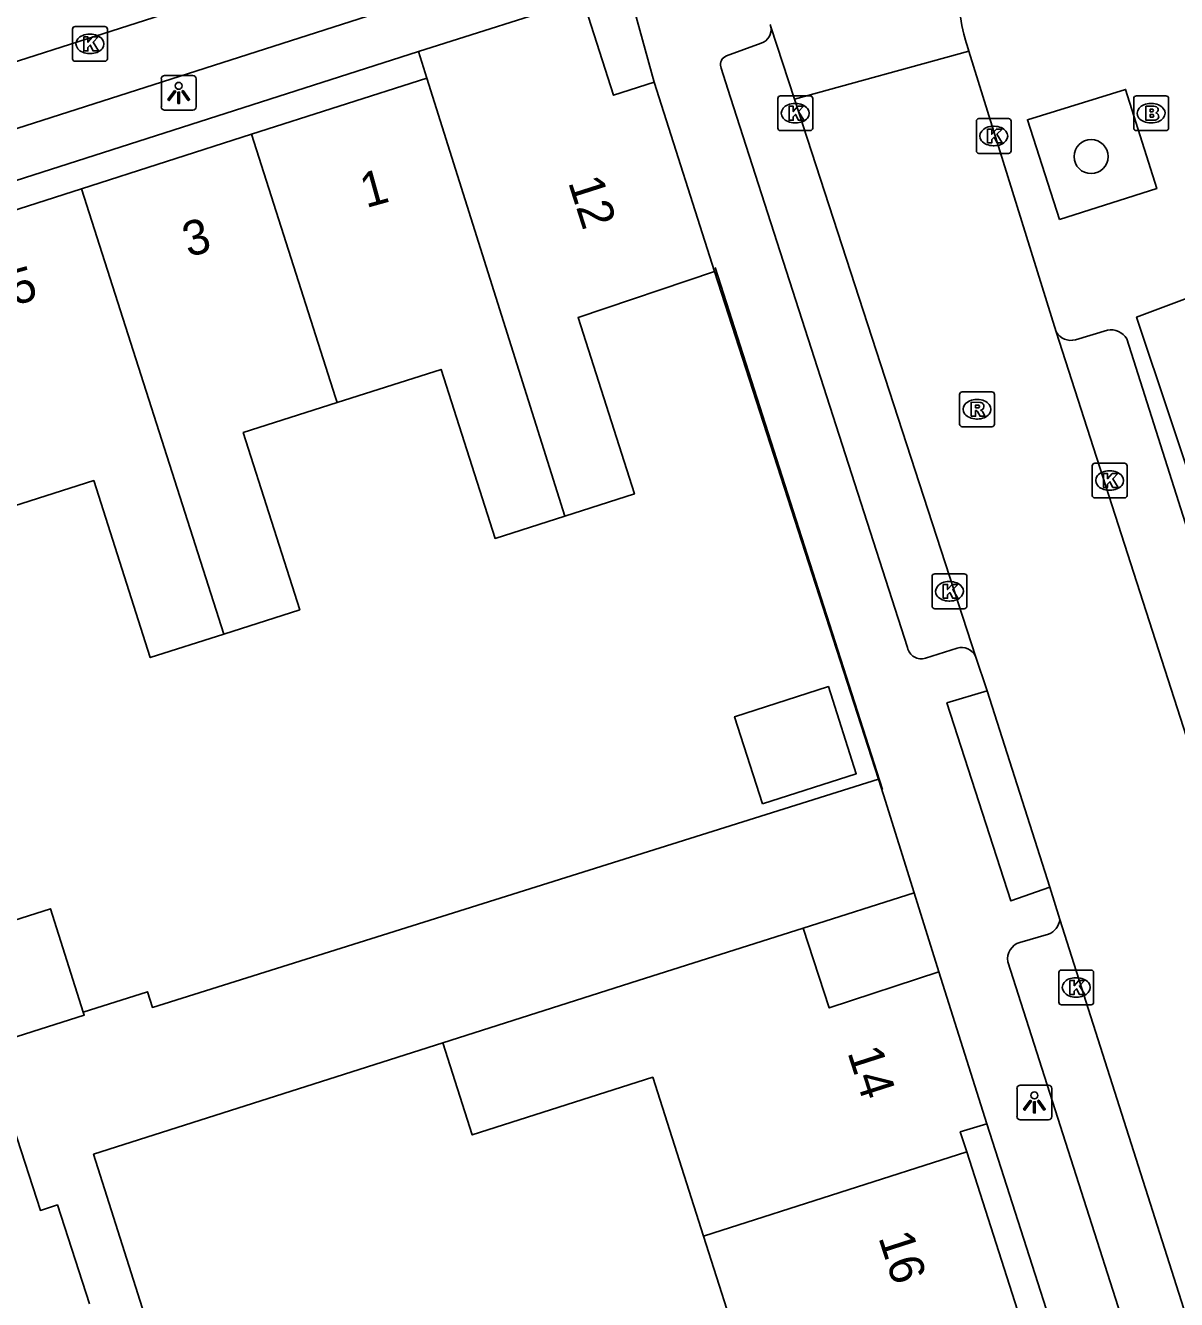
# Model space of a CAD drawing. Extents: x 159718 to 160783, y 383290 to 384030.
# Drawn here: x 160111.85 to 160144.93, y 383640.55 to 383677.17 of the extents above; entities that cross this region are included whole.
import ezdxf

# ---------------------------------------------------------------- set-up
doc = ezdxf.new("R2010")
doc.units = 0
for name, color, linetype in [('IMGEO_Boom', 7, 'Continuous'), ('IMGEO_Brandkraan', 7, 'Continuous'), ('IMGEO_Kolk', 7, 'Continuous'), ('IMGEO_Lichtpunt', 7, 'Continuous'), ('IMGEO_Muur', 7, 'Continuous'), ('IMGEO_Pand', 7, 'Continuous'), ('IMGEO_Pand_nummerreeks', 7, 'Continuous'), ('IMGEO_Rijbaan_lokaal_open', 7, 'Continuous'), ('IMGEO_Rioolput', 7, 'Continuous'), ('IMGEO_Voetpad_open', 7, 'Continuous')]:
    doc.layers.add(name, color=color, linetype=linetype)

msp = doc.modelspace()

# ---------------------------------------------------------------- linework, layer by layer
at = {"layer": 'IMGEO_Boom'}
msp.add_circle((160142.474, 383673.403), 0.489, dxfattribs=at)
at = {"layer": 'IMGEO_Brandkraan'}
for p, q in [((160143.699, 383674.224), (160143.699, 383675.076)), ((160143.774, 383675.15), (160144.626, 383675.15)), ((160144.187, 383674.93), (160144.212, 383674.93)), ((160144.7, 383675.076), (160144.7, 383674.224)), ((160144.626, 383674.15), (160143.774, 383674.15)), ((160144.21, 383674.37), (160144.185, 383674.37))]:
    msp.add_line(p, q, dxfattribs=at)
for points in [[(160143.699, 383674.224), (160143.699, 383675.076)], [(160143.774, 383675.15), (160144.626, 383675.15)], [(160144.047, 383674.85), (160144.047, 383674.45), (160144.26, 383674.45)], [(160144.278, 383674.85), (160144.047, 383674.85)], [(160144.7, 383675.076), (160144.7, 383674.224)], [(160144.226, 383674.769), (160144.172, 383674.769), (160144.172, 383674.693)], [(160144.172, 383674.693), (160144.225, 383674.693)], [(160144.234, 383674.617), (160144.172, 383674.617), (160144.172, 383674.536)], [(160144.172, 383674.536), (160144.234, 383674.536)], [(160144.626, 383674.15), (160143.774, 383674.15)]]:
    msp.add_lwpolyline(points, dxfattribs=at)
for centre, radius, start, end in [((160143.776, 383675.074), 0.0765, 91.552, 178.448), ((160143.776, 383675.074), 0.0765, 91.552, 178.448), ((160144.282, 383674.705), 0.145, 59.4692, 91.5367), ((160144.307, 383674.752), 0.0922, 285.5137, 58.1501), ((160144.624, 383675.074), 0.0765, 1.552, 88.448), ((160144.624, 383675.074), 0.0765, 1.552, 88.448), ((160144.227, 383674.731), 0.0379, 267.8285, 90.9355), ((160144.235, 383674.576), 0.0404, 269.8759, 90.5077), ((160144.266, 383674.701), 0.251, 268.6676, 293.5347), ((160144.312, 383674.56), 0.105, 301.3115, 78.989), ((160143.776, 383674.226), 0.0765, 181.552, 268.448), ((160143.776, 383674.226), 0.0765, 181.552, 268.448), ((160144.624, 383674.226), 0.0765, 271.552, 358.448), ((160144.624, 383674.226), 0.0765, 271.552, 358.448)]:
    msp.add_arc(centre, radius, start, end, dxfattribs=at)
for centre, major_axis, ratio, start_param, end_param in [((160144.186, 383674.65), (-0.387, 0.002), 0.722429, 4.712389, 7.853982), ((160144.211, 383674.65), (-0.39, 0.002), 0.717154, 1.570796, 4.712389)]:
    msp.add_ellipse(centre, major_axis=major_axis, ratio=ratio, start_param=start_param, end_param=end_param, dxfattribs=at)
at = {"layer": 'IMGEO_Kolk'}
for p, q in [((160113.203, 383676.217), (160113.203, 383677.069)), ((160113.278, 383677.143), (160114.13, 383677.143)), ((160114.204, 383677.069), (160114.204, 383676.217)), ((160113.691, 383676.923), (160113.716, 383676.923)), ((160113.714, 383676.363), (160113.689, 383676.363)), ((160114.13, 383676.143), (160113.278, 383676.143)), ((160133.472, 383674.223), (160133.472, 383675.075)), ((160133.547, 383675.149), (160134.399, 383675.149)), ((160133.96, 383674.929), (160133.985, 383674.929)), ((160134.473, 383675.075), (160134.473, 383674.223)), ((160139.252, 383674.495), (160140.104, 383674.495)), ((160134.399, 383674.149), (160133.547, 383674.149)), ((160133.983, 383674.369), (160133.958, 383674.369)), ((160139.177, 383673.569), (160139.177, 383674.421)), ((160139.665, 383674.275), (160139.69, 383674.275)), ((160140.178, 383674.421), (160140.178, 383673.569)), ((160139.688, 383673.715), (160139.663, 383673.715)), ((160140.104, 383673.495), (160139.252, 383673.495)), ((160142.581, 383664.592), (160143.433, 383664.592)), ((160142.506, 383663.666), (160142.506, 383664.518)), ((160142.994, 383664.372), (160143.019, 383664.372)), ((160143.507, 383664.518), (160143.507, 383663.666)), ((160143.017, 383663.812), (160142.992, 383663.812)), ((160143.433, 383663.592), (160142.581, 383663.592)), ((160137.904, 383660.482), (160137.904, 383661.334)), ((160137.979, 383661.408), (160138.831, 383661.408)), ((160138.905, 383661.334), (160138.905, 383660.482)), ((160138.392, 383661.188), (160138.417, 383661.188)), ((160138.415, 383660.628), (160138.39, 383660.628)), ((160138.831, 383660.408), (160137.979, 383660.408)), ((160141.545, 383649.096), (160141.545, 383649.948)), ((160141.62, 383650.022), (160142.472, 383650.022)), ((160142.546, 383649.948), (160142.546, 383649.096)), ((160142.033, 383649.802), (160142.058, 383649.802)), ((160142.056, 383649.242), (160142.031, 383649.242)), ((160142.472, 383649.022), (160141.62, 383649.022))]:
    msp.add_line(p, q, dxfattribs=at)
for points in [[(160113.203, 383676.217), (160113.203, 383677.069)], [(160113.278, 383677.143), (160114.13, 383677.143)], [(160114.204, 383677.069), (160114.204, 383676.217)], [(160113.524, 383676.843), (160113.647, 383676.843), (160113.647, 383676.692), (160113.777, 383676.843), (160113.941, 383676.843), (160113.795, 383676.692), (160113.948, 383676.443), (160113.796, 383676.443), (160113.711, 383676.607), (160113.647, 383676.54), (160113.647, 383676.443), (160113.524, 383676.443), (160113.524, 383676.843)], [(160114.13, 383676.143), (160113.278, 383676.143)], [(160133.472, 383674.223), (160133.472, 383675.075)], [(160133.547, 383675.149), (160134.399, 383675.149)], [(160133.793, 383674.849), (160133.916, 383674.849), (160133.916, 383674.698), (160134.046, 383674.849), (160134.21, 383674.849), (160134.064, 383674.698), (160134.217, 383674.449), (160134.065, 383674.449), (160133.98, 383674.613), (160133.916, 383674.546), (160133.916, 383674.449), (160133.793, 383674.449), (160133.793, 383674.849)], [(160134.473, 383675.075), (160134.473, 383674.223)], [(160139.252, 383674.495), (160140.104, 383674.495)], [(160134.399, 383674.149), (160133.547, 383674.149)], [(160139.177, 383673.569), (160139.177, 383674.421)], [(160139.498, 383674.195), (160139.621, 383674.195), (160139.621, 383674.044), (160139.751, 383674.195), (160139.915, 383674.195), (160139.769, 383674.044), (160139.922, 383673.795), (160139.77, 383673.795), (160139.685, 383673.959), (160139.621, 383673.892), (160139.621, 383673.795), (160139.498, 383673.795), (160139.498, 383674.195)], [(160140.178, 383674.421), (160140.178, 383673.569)], [(160140.104, 383673.495), (160139.252, 383673.495)], [(160142.581, 383664.592), (160143.433, 383664.592)], [(160142.506, 383663.666), (160142.506, 383664.518)], [(160142.827, 383664.292), (160142.95, 383664.292), (160142.95, 383664.141), (160143.08, 383664.292), (160143.244, 383664.292), (160143.098, 383664.141), (160143.251, 383663.892), (160143.099, 383663.892), (160143.014, 383664.056), (160142.95, 383663.989), (160142.95, 383663.892), (160142.827, 383663.892), (160142.827, 383664.292)], [(160143.507, 383664.518), (160143.507, 383663.666)], [(160143.433, 383663.592), (160142.581, 383663.592)], [(160137.904, 383660.482), (160137.904, 383661.334)], [(160137.979, 383661.408), (160138.831, 383661.408)], [(160138.905, 383661.334), (160138.905, 383660.482)], [(160138.225, 383661.108), (160138.348, 383661.108), (160138.348, 383660.957), (160138.478, 383661.108), (160138.642, 383661.108), (160138.496, 383660.957), (160138.649, 383660.708), (160138.497, 383660.708), (160138.412, 383660.872), (160138.348, 383660.805), (160138.348, 383660.708), (160138.225, 383660.708), (160138.225, 383661.108)], [(160138.831, 383660.408), (160137.979, 383660.408)], [(160141.545, 383649.096), (160141.545, 383649.948)], [(160141.62, 383650.022), (160142.472, 383650.022)], [(160142.546, 383649.948), (160142.546, 383649.096)], [(160141.866, 383649.722), (160141.989, 383649.722), (160141.989, 383649.571), (160142.119, 383649.722), (160142.283, 383649.722), (160142.137, 383649.571), (160142.29, 383649.322), (160142.138, 383649.322), (160142.053, 383649.486), (160141.989, 383649.419), (160141.989, 383649.322), (160141.866, 383649.322), (160141.866, 383649.722)], [(160142.472, 383649.022), (160141.62, 383649.022)]]:
    msp.add_lwpolyline(points, dxfattribs=at)
for centre, start, end in [((160113.28, 383677.067), 91.552, 178.448), ((160113.28, 383677.067), 91.552, 178.448), ((160114.128, 383677.067), 1.552, 88.448), ((160114.128, 383677.067), 1.552, 88.448), ((160113.28, 383676.219), 181.552, 268.448), ((160113.28, 383676.219), 181.552, 268.448), ((160114.128, 383676.219), 271.552, 358.448), ((160114.128, 383676.219), 271.552, 358.448), ((160133.549, 383675.073), 91.552, 178.448), ((160133.549, 383675.073), 91.552, 178.448), ((160134.397, 383675.073), 1.552, 88.448), ((160134.397, 383675.073), 1.552, 88.448), ((160139.254, 383674.419), 91.552, 178.448), ((160139.254, 383674.419), 91.552, 178.448), ((160140.102, 383674.419), 1.552, 88.448), ((160140.102, 383674.419), 1.552, 88.448), ((160133.549, 383674.225), 181.552, 268.448), ((160133.549, 383674.225), 181.552, 268.448), ((160134.397, 383674.225), 271.552, 358.448), ((160134.397, 383674.225), 271.552, 358.448), ((160139.254, 383673.571), 181.552, 268.448), ((160139.254, 383673.571), 181.552, 268.448), ((160140.102, 383673.571), 271.552, 358.448), ((160140.102, 383673.571), 271.552, 358.448), ((160142.583, 383664.516), 91.552, 178.448), ((160142.583, 383664.516), 91.552, 178.448), ((160143.431, 383664.516), 1.552, 88.448), ((160143.431, 383664.516), 1.552, 88.448), ((160142.583, 383663.668), 181.552, 268.448), ((160142.583, 383663.668), 181.552, 268.448), ((160143.431, 383663.668), 271.552, 358.448), ((160143.431, 383663.668), 271.552, 358.448), ((160137.981, 383661.332), 91.552, 178.448), ((160137.981, 383661.332), 91.552, 178.448), ((160138.829, 383661.332), 1.552, 88.448), ((160138.829, 383661.332), 1.552, 88.448), ((160137.981, 383660.484), 181.552, 268.448), ((160137.981, 383660.484), 181.552, 268.448), ((160138.829, 383660.484), 271.552, 358.448), ((160138.829, 383660.484), 271.552, 358.448), ((160141.622, 383649.946), 91.552, 178.448), ((160141.622, 383649.946), 91.552, 178.448), ((160142.47, 383649.946), 1.552, 88.448), ((160142.47, 383649.946), 1.552, 88.448), ((160141.622, 383649.098), 181.552, 268.448), ((160141.622, 383649.098), 181.552, 268.448), ((160142.47, 383649.098), 271.552, 358.448), ((160142.47, 383649.098), 271.552, 358.448)]:
    msp.add_arc(centre, 0.0765, start, end, dxfattribs=at)
for centre, major_axis, ratio, start_param, end_param in [((160113.69, 383676.643), (-0.387, 0.002), 0.722429, 4.712389, 7.853982), ((160113.715, 383676.643), (-0.39, 0.002), 0.717154, 1.570796, 4.712389), ((160133.959, 383674.649), (-0.387, 0.002), 0.722429, 4.712389, 7.853982), ((160133.984, 383674.649), (-0.39, 0.002), 0.717154, 1.570796, 4.712389), ((160139.664, 383673.995), (-0.387, 0.002), 0.722429, 4.712389, 7.853982), ((160139.689, 383673.995), (-0.39, 0.002), 0.717154, 1.570796, 4.712389), ((160142.993, 383664.092), (-0.387, 0.002), 0.722429, 4.712389, 7.853982), ((160143.018, 383664.092), (-0.39, 0.002), 0.717154, 1.570796, 4.712389), ((160138.391, 383660.908), (-0.387, 0.002), 0.722429, 4.712389, 7.853982), ((160138.416, 383660.908), (-0.39, 0.002), 0.717154, 1.570796, 4.712389), ((160142.032, 383649.522), (-0.387, 0.002), 0.722429, 4.712389, 7.853982), ((160142.057, 383649.522), (-0.39, 0.002), 0.717154, 1.570796, 4.712389)]:
    msp.add_ellipse(centre, major_axis=major_axis, ratio=ratio, start_param=start_param, end_param=end_param, dxfattribs=at)
at = {"layer": 'IMGEO_Lichtpunt'}
for p, q in [((160115.756, 383675.639), (160115.756, 383674.832)), ((160115.756, 383675.639), (160115.756, 383674.832)), ((160116.658, 383675.734), (160115.85, 383675.734)), ((160116.658, 383675.734), (160115.85, 383675.734)), ((160116.752, 383674.832), (160116.752, 383675.639)), ((160116.752, 383674.832), (160116.752, 383675.639)), ((160115.85, 383674.738), (160116.658, 383674.738)), ((160115.85, 383674.738), (160116.658, 383674.738)), ((160140.345, 383646.619), (160140.345, 383645.812)), ((160140.345, 383646.619), (160140.345, 383645.812)), ((160141.247, 383646.714), (160140.439, 383646.714)), ((160141.247, 383646.714), (160140.439, 383646.714)), ((160141.341, 383645.812), (160141.341, 383646.619)), ((160141.341, 383645.812), (160141.341, 383646.619)), ((160140.439, 383645.718), (160141.247, 383645.718)), ((160140.439, 383645.718), (160141.247, 383645.718))]:
    msp.add_line(p, q, dxfattribs=at)
for points in [[(160116.13, 383675.303), (160116.169, 383675.275), (160115.981, 383675.013), (160115.943, 383675.04), (160116.13, 383675.303)], [(160116.232, 383675.255), (160116.279, 383675.255), (160116.279, 383674.933), (160116.232, 383674.933), (160116.232, 383675.255)], [(160116.342, 383675.275), (160116.38, 383675.302), (160116.567, 383675.04), (160116.528, 383675.012), (160116.342, 383675.275)], [(160140.719, 383646.283), (160140.758, 383646.255), (160140.57, 383645.993), (160140.532, 383646.02), (160140.719, 383646.283)], [(160140.821, 383646.235), (160140.868, 383646.235), (160140.868, 383645.913), (160140.821, 383645.913), (160140.821, 383646.235)], [(160140.931, 383646.255), (160140.969, 383646.282), (160141.156, 383646.02), (160141.117, 383645.992), (160140.931, 383646.255)]]:
    msp.add_lwpolyline(points, dxfattribs=at)
for centre in [(160116.255, 383675.437), (160140.844, 383646.417)]:
    msp.add_circle(centre, 0.0994, dxfattribs=at)
for centre, start, end in [((160115.85, 383675.639), 90, 180), ((160115.85, 383675.639), 90, 180), ((160116.658, 383675.639), 0, 90), ((160116.658, 383675.639), 0, 90), ((160115.85, 383674.832), 180, 270), ((160115.85, 383674.832), 180, 270), ((160116.658, 383674.832), 270, 0), ((160116.658, 383674.832), 270, 360), ((160140.439, 383646.619), 90, 180), ((160140.439, 383646.619), 90, 180), ((160141.247, 383646.619), 0, 90), ((160141.247, 383646.619), 0, 90), ((160140.439, 383645.812), 180, 270), ((160140.439, 383645.812), 180, 270), ((160141.247, 383645.812), 270, 0), ((160141.247, 383645.812), 270, 360)]:
    msp.add_arc(centre, 0.0946, start, end, dxfattribs=at)
at = {"layer": 'IMGEO_Muur'}
msp.add_lwpolyline([(160131.667, 383670.211), (160136.481, 383655.215)], dxfattribs=at)
at = {"layer": 'IMGEO_Pand'}
for points in [[(160123.144, 383676.422), (160127.87, 383677.928), (160128.746, 383675.167), (160129.915, 383675.538)], [(160123.386, 383675.66), (160123.144, 383676.422)], [(160123.386, 383675.66), (160118.342, 383674.043)], [(160127.35, 383663.067), (160123.386, 383675.66)], [(160131.65, 383670.104), (160129.915, 383675.538)], [(160118.342, 383674.043), (160113.462, 383672.478)], [(160120.805, 383666.331), (160120.758, 383666.478), (160118.342, 383674.043)], [(160108.583, 383670.914), (160113.462, 383672.478)], [(160113.462, 383672.478), (160117.551, 383659.679)], [(160127.35, 383663.067), (160129.351, 383663.706), (160127.73, 383668.779), (160131.65, 383670.104)], [(160120.805, 383666.331), (160123.796, 383667.287), (160125.347, 383662.428), (160127.35, 383663.067)], [(160117.551, 383659.679), (160119.734, 383660.377), (160118.108, 383665.469), (160120.805, 383666.331)], [(160111.044, 383663.207), (160113.814, 383664.092), (160115.439, 383659.005), (160117.551, 383659.679)], [(160133.029, 383654.803), (160135.726, 383655.666), (160134.927, 383658.167), (160132.229, 383657.304), (160133.029, 383654.803)], [(160110.518, 383647.867), (160109.579, 383650.836), (160112.572, 383651.783), (160113.511, 383648.814)], [(160123.842, 383647.93), (160129.46, 383649.725), (160134.204, 383651.225)], [(160134.204, 383651.225), (160134.948, 383648.933), (160138.096, 383649.97)], [(160138.096, 383649.97), (160139.479, 383645.604)], [(160113.511, 383648.814), (160113.539, 383648.726), (160110.546, 383647.779), (160110.518, 383647.867)], [(160131.338, 383642.375), (160129.878, 383646.942), (160124.688, 383645.283), (160123.842, 383647.93)], [(160139.479, 383645.604), (160138.715, 383645.368), (160138.9, 383644.792)], [(160138.9, 383644.792), (160131.607, 383642.462), (160131.338, 383642.375)], [(160140.434, 383640.007), (160138.9, 383644.792)], [(160131.338, 383642.375), (160132.087, 383640.033), (160127.896, 383638.693), (160128.678, 383636.249)]]:
    msp.add_lwpolyline(points, dxfattribs=at)
at = {"layer": 'IMGEO_Rijbaan_lokaal_open'}
for points in [[(160097.72, 383671.705), (160127.305, 383681.179)], [(160133.272, 383677.136), (160133.252, 383677.2)], [(160133.948, 383675.056), (160133.272, 383677.136)], [(160138.962, 383676.438), (160133.948, 383675.056)], [(160138.962, 383676.438), (160141.47, 383668.37)], [(160141.567, 383671.596), (160140.646, 383674.463), (160143.464, 383675.334), (160144.362, 383672.483), (160141.567, 383671.596)], [(160133.948, 383675.056), (160139.151, 383659.043)], [(160145.734, 383662.939), (160143.781, 383668.791), (160145.234, 383669.335), (160147.143, 383663.407), (160145.734, 383662.939)], [(160156.009, 383623.174), (160141.47, 383668.37)], [(160142.023, 383668.14), (160142.942, 383668.415)], [(160143.499, 383668.167), (160153.963, 383635.229), (160166.59, 383596.057)], [(160139.483, 383658.043), (160139.151, 383659.043)], [(160139.483, 383658.043), (160141.29, 383652.4)], [(160141.576, 383651.473), (160141.29, 383652.4)], [(160141.576, 383651.473), (160148.415, 383629.989), (160151.141, 383621.545)]]:
    msp.add_lwpolyline(points, dxfattribs=at)
for centre, radius, start, end in [((160143.65, 383678.101), 4.974, 106.9878, 199.5257), ((160141.889, 383668.596), 0.476, 208.419, 286.4148), ((160143.041, 383667.888), 0.536, 31.3359, 100.6628)]:
    msp.add_arc(centre, radius, start, end, dxfattribs=at)
at = {"layer": 'IMGEO_Rioolput'}
for p, q in [((160138.695, 383665.714), (160138.695, 383666.566)), ((160138.77, 383666.64), (160139.622, 383666.64)), ((160139.183, 383666.42), (160139.208, 383666.42)), ((160139.696, 383666.566), (160139.696, 383665.714)), ((160139.622, 383665.64), (160138.77, 383665.64)), ((160139.206, 383665.86), (160139.181, 383665.86))]:
    msp.add_line(p, q, dxfattribs=at)
for points in [[(160138.695, 383665.714), (160138.695, 383666.566)], [(160138.77, 383666.64), (160139.622, 383666.64)], [(160139.696, 383666.566), (160139.696, 383665.714)], [(160139.284, 383666.338), (160139.032, 383666.34), (160139.032, 383665.94)], [(160139.032, 383665.94), (160139.156, 383665.94), (160139.156, 383666.102), (160139.167, 383666.102)], [(160139.21, 383666.259), (160139.156, 383666.259), (160139.156, 383666.178)], [(160139.156, 383666.178), (160139.208, 383666.178)], [(160139.214, 383666.073), (160139.285, 383665.94), (160139.425, 383665.94), (160139.36, 383666.066)], [(160139.622, 383665.64), (160138.77, 383665.64)]]:
    msp.add_lwpolyline(points, dxfattribs=at)
for centre, radius, start, end in [((160138.772, 383666.564), 0.0765, 91.552, 178.448), ((160138.772, 383666.564), 0.0765, 91.552, 178.448), ((160139.62, 383666.564), 0.0765, 1.552, 88.448), ((160139.62, 383666.564), 0.0765, 1.552, 88.448), ((160139.166, 383666.049), 0.0533, 26.0293, 88.6989), ((160139.192, 383666.367), 0.19, 274.7715, 282.9687), ((160139.216, 383666.163), 0.0964, 77.0061, 93.1865), ((160139.23, 383666.22), 0.0378, 276.6634, 79.6772), ((160139.283, 383666.228), 0.109, 350.3612, 89.416), ((160139.281, 383666.228), 0.112, 277.5842, 350.9817), ((160139.265, 383666.013), 0.108, 29.5134, 73.7905), ((160138.772, 383665.716), 0.0765, 181.552, 268.448), ((160138.772, 383665.716), 0.0765, 181.552, 268.448), ((160139.62, 383665.716), 0.0765, 271.552, 358.448), ((160139.62, 383665.716), 0.0765, 271.552, 358.448)]:
    msp.add_arc(centre, radius, start, end, dxfattribs=at)
for centre, major_axis, ratio, start_param, end_param in [((160139.182, 383666.14), (-0.387, 0.002), 0.722429, 4.712389, 7.853982), ((160139.207, 383666.14), (-0.39, 0.002), 0.717154, 1.570796, 4.712389)]:
    msp.add_ellipse(centre, major_axis=major_axis, ratio=ratio, start_param=start_param, end_param=end_param, dxfattribs=at)
at = {"layer": 'IMGEO_Voetpad_open'}
for points in [[(160129.915, 383675.538), (160128.426, 383680.973)], [(160127.096, 383679.187), (160099.065, 383670.2)], [(160131.993, 383676.295), (160132.988, 383676.665)], [(160103.512, 383670.129), (160123.144, 383676.422)], [(160137.195, 383659.29), (160132.115, 383675.101), (160131.833, 383675.978)], [(160131.65, 383670.104), (160136.361, 383655.511)], [(160138.626, 383659.275), (160137.717, 383658.983)], [(160141.29, 383652.4), (160140.166, 383652.01), (160138.333, 383657.7), (160139.483, 383658.043)], [(160136.361, 383655.511), (160115.5, 383648.947), (160115.357, 383649.398), (160113.511, 383648.814)], [(160136.361, 383655.511), (160136.509, 383655.053), (160137.393, 383652.245)], [(160134.204, 383651.225), (160137.393, 383652.245)], [(160137.393, 383652.245), (160138.096, 383649.97)], [(160140.43, 383650.813), (160141.248, 383651.051)], [(160158.444, 383593.145), (160156.603, 383598.576), (160140.081, 383650.261)], [(160104.211, 383594.364), (160110.764, 383596.41), (160127.456, 383601.679), (160120.476, 383623.696), (160119.09, 383628.068), (160113.81, 383644.725), (160123.842, 383647.93)], [(160110.921, 383645.315), (160111.509, 383645.501), (160112.28, 383643.114), (160112.77, 383643.272), (160113.688, 383640.429)], [(160139.479, 383645.604), (160155.168, 383596.67)]]:
    msp.add_lwpolyline(points, dxfattribs=at)
for centre, radius, start, end in [((160132.875, 383677.054), 0.406, 286.2164, 11.6059), ((160132.087, 383676.049), 0.264, 110.9387, 195.4982), ((160137.601, 383659.383), 0.417, 192.9303, 286.1482), ((160138.753, 383658.852), 0.442, 25.65, 106.6683), ((160141.062, 383651.534), 0.518, 291.0818, 353.2058), ((160140.56, 383650.344), 0.487, 105.5441, 189.85)]:
    msp.add_arc(centre, radius, start, end, dxfattribs=at)

# ---------------------------------------------------------------- texts
at = {"layer": 'IMGEO_Pand_nummerreeks'}
for s, rotation, p in [('1', 15.4985, (160121.636, 383671.92)), ('12', 287.7271, (160127.439, 383672.668)), ('3', 15.4985, (160116.531, 383670.506)), ('5', 15.4985, (160111.537, 383669.121)), ('14', 287.8532, (160135.465, 383647.655)), ('16', 287.8474, (160136.354, 383642.338))]:
    msp.add_text(s, height=1, rotation=rotation, dxfattribs=at).set_placement(p)

doc.saveas('drawing.dxf')
